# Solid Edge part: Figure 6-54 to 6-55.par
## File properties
Author: Ashutosh-CADCIM
Template: Iso Metric Part.par
Last saved by: Ashutosh-CADCIM
Revision: 1
Application: Solid Edge
Accuracy: 0.990
Username: Ashutosh-CADCIM
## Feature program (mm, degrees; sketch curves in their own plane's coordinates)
sketch for "unnamed Protrusion 1" plane through (0, 0, 0) normal (0, 0, 1) x-axis (1, 0, 0)
  line (-100, -100) -> (100, -100)
  line (100, -100) -> (100, 100)
  line (100, 100) -> (-100, 100)
  line (-100, 100) -> (-100, -100)
extrude "unnamed Protrusion 1" add finite 20 symmetric
sketch for "Hole_1" plane through (0, 0, 10) normal (0, 0, 1) x-axis (0, 1, 0)
  hole centre (0, 80) bore radius 6
hole "Hole_1" diameter 12 through  CounterBoreDepth = 10.8 mm
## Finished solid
Body 1: solid body, 9 faces, 16 edges, 8 vertices.
  Faces by surface: plane 7, cylinder 2
  Edges by curve: line 12, circle 4
Bounding box of the edges (mm): 200.000 x 200.000 x 20.000, from (-100, -100, -10) to (100, 100, 10).
Cylindrical faces by radius (mm): R6 x1, R9 x1
Planar faces by outward normal: +x 1, +y 1, +z 2, -x 1, -y 1, -z 1
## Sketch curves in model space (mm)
spline (-80, 0, 10) -> (84.2541, 54.6419, 10) -> (-80, 68.3566, 10)
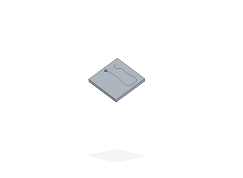
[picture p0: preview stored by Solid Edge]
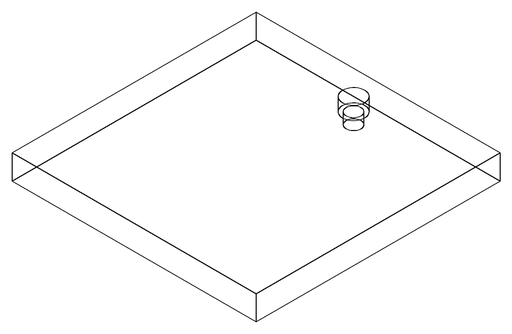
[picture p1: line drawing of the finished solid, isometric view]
